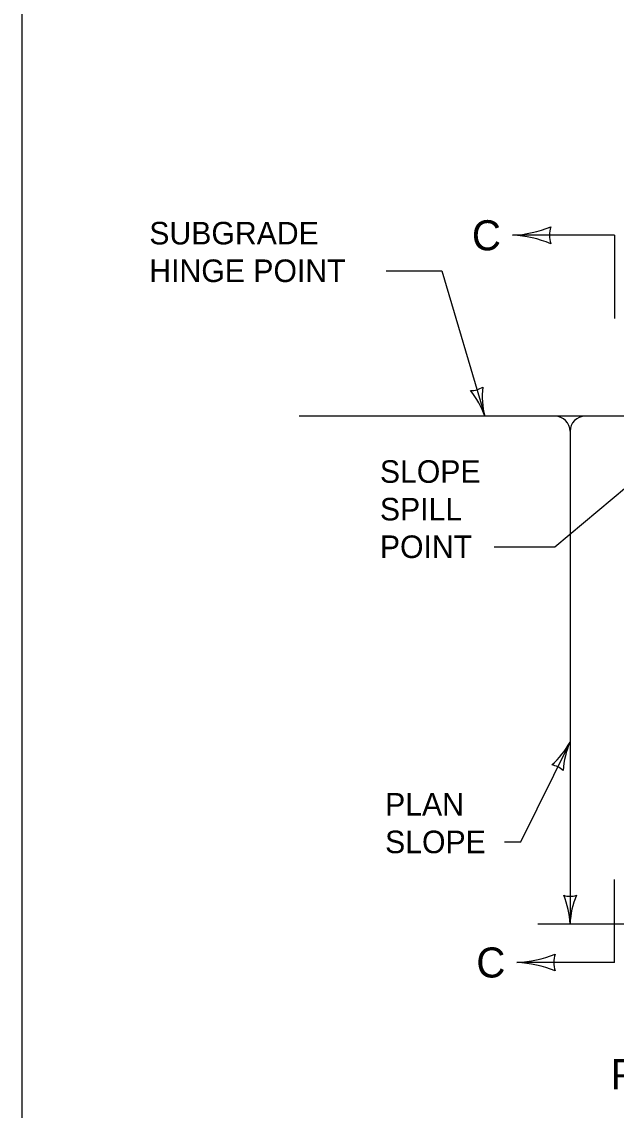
# Model space of a CAD drawing. Extents: x 49991.4 to 50021, y 49987.6 to 50011.4.
# Drawn here: x 50000.336 to 50001.915, y 50002.562 to 50005.456 of the extents above; entities that cross this region are included whole.
import ezdxf

# ---------------------------------------------------------------- set-up
doc = ezdxf.new("R2010")
doc.units = 0
for name, color, linetype in [('Level 1', 7, 'Continuous'), ('Level 2', 7, 'Continuous'), ('Level 3', 7, 'Continuous'), ('Level 6', 7, 'Continuous')]:
    doc.layers.add(name, color=color, linetype=linetype)

msp = doc.modelspace()

# ---------------------------------------------------------------- linework, layer by layer
at = {"layer": 'Level 1'}
for p, q in [((50002.1471, 50004.407), (50001.0722, 50004.407)), ((50001.7071, 50003.057), (50002.0471, 50003.057))]:
    msp.add_line(p, q, dxfattribs=at)
msp.add_lwpolyline([(50008.6146, 50011.2628), (50000.3356, 50011.2628), (50000.3356, 50000.0624), (50008.6146, 50000.0624)], close=True, dxfattribs=at)
at = {"layer": 'Level 3'}
for p, q in [((50001.3038, 50004.7939), (50001.4517, 50004.7939)), ((50001.4517, 50004.7939), (50001.5658, 50004.407)), ((50001.7924, 50004.367), (50001.7924, 50003.057)), ((50001.7521, 50004.06), (50002.0471, 50004.307)), ((50001.5909, 50004.06), (50001.7521, 50004.06)), ((50001.6616, 50003.2751), (50001.7924, 50003.5406)), ((50001.6185, 50003.2751), (50001.6616, 50003.2751))]:
    msp.add_line(p, q, dxfattribs=at)
for centre, radius, start, end in [((50001.6243, 50005.1986), 0.3107, 272.8273, 292.0772), ((50001.8106, 50004.8883), 0.073, 162.1388, 197.8612), ((50001.6274, 50004.5921), 0.2964, 67.456, 87.6395), ((50001.5295, 50004.53), 0.0548, 268.5662, 304.2886), ((50001.3458, 50004.3302), 0.233, 19.2547, 38.5046), ((50001.7814, 50004.4611), 0.2223, 173.8834, 194.0669), ((50001.7524, 50004.367), 0.04, 0, 90), ((50001.8324, 50004.367), 0.04, 90, 180), ((50001.5972, 50003.6469), 0.2223, 311.2353, 331.4188), ((50002.0062, 50003.4481), 0.233, 156.6066, 175.8565), ((50001.7358, 50003.4255), 0.0548, 45.9181, 81.6405), ((50001.7924, 50003.1852), 0.0548, 252.1388, 287.8612), ((50001.5597, 50003.0455), 0.233, 2.8273, 22.0772), ((50002.0145, 50003.0479), 0.2223, 157.456, 177.6395), ((50001.636, 50003.2647), 0.3107, 272.8273, 292.0772), ((50001.8223, 50002.9544), 0.073, 162.1388, 197.8612), ((50001.6391, 50002.6582), 0.2964, 67.456, 87.6395)]:
    msp.add_arc(centre, radius, start, end, dxfattribs=at)
at = {"layer": 'Level 6'}
for p, q in [((50001.9102, 50004.8883), (50001.6396, 50004.8883)), ((50001.9102, 50004.8883), (50001.9102, 50004.6672)), ((50001.9102, 50002.9544), (50001.9102, 50003.1755)), ((50001.9102, 50002.9544), (50001.6513, 50002.9544))]:
    msp.add_line(p, q, dxfattribs=at)

# ---------------------------------------------------------------- texts
at = {"layer": 'Level 2'}
for s, height, p in [('C', 0.0799, (50001.5316, 50004.8483)), ('SUBGRADE ', 0.06, (50000.6744, 50004.8639)), ('HINGE POINT', 0.06, (50000.6744, 50004.7639)), ('SLOPE', 0.06, (50001.2871, 50004.23)), ('SPILL ', 0.06, (50001.2871, 50004.13)), ('POINT', 0.06, (50001.2871, 50004.03)), ('PLAN', 0.06, (50001.3009, 50003.3451)), ('SLOPE', 0.06, (50001.3009, 50003.2451)), ('C', 0.0799, (50001.5433, 50002.9145)), ('PLAN VIEW', 0.08, (50001.9, 50002.6175))]:
    msp.add_text(s, height=height, dxfattribs=at).set_placement(p)

doc.saveas('drawing.dxf')
